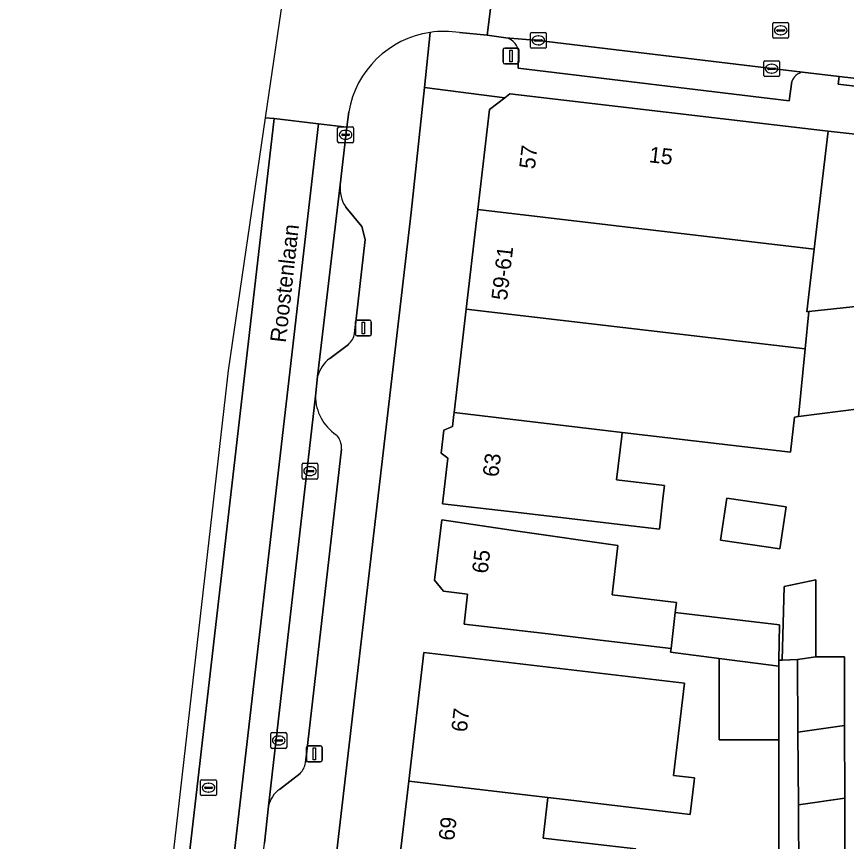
# Model space of a CAD drawing. Extents: x 162250 to 162661, y 380743 to 381606.
# Drawn here: x 162302.6 to 162355, y 381314.8 to 381366.9 of the extents above; entities that cross this region are included whole.
import ezdxf

# ---------------------------------------------------------------- set-up
doc = ezdxf.new("R2010")
doc.units = 0
for name, color, linetype in [('IMGEO_Erf', 7, 'Continuous'), ('IMGEO_Kolk', 7, 'Continuous'), ('IMGEO_Lichtmast', 7, 'Continuous'), ('IMGEO_Openbare_ruimte_label', 7, 'Continuous'), ('IMGEO_Pand', 7, 'Continuous'), ('IMGEO_Pand_nummerreeks', 7, 'Continuous'), ('IMGEO_Parkeervlak_open', 7, 'Continuous'), ('IMGEO_Rijbaan_lokaal_gesloten', 7, 'Continuous'), ('IMGEO_Rijbaan_lokaal_open', 7, 'Continuous'), ('IMGEO_Rioolput', 7, 'Continuous'), ('IMGEO_Voetpad_open', 7, 'Continuous')]:
    doc.layers.add(name, color=color, linetype=linetype)

msp = doc.modelspace()

# ---------------------------------------------------------------- linework, layer by layer
at = {"layer": 'IMGEO_Erf'}
for points in [[(162357.316, 381342.327), (162352.007, 381341.645), (162351.764, 381341.614), (162351.504, 381339.396), (162340.872, 381340.643), (162340.843, 381340.397), (162340.52, 381337.645), (162343.543, 381337.291), (162343.465, 381336.631), (162343.226, 381334.524), (162334.488, 381335.549), (162329.522, 381336.131), (162329.86, 381339.014), (162329.432, 381339.332), (162329.603, 381340.791), (162330.142, 381341.023), (162330.23, 381341.78), (162330.243, 381341.891), (162331.011, 381348.438), (162331.669, 381354.046), (162331.704, 381354.344), (162331.749, 381354.725), (162332.491, 381361.05), (162333.445, 381361.804), (162328.382, 381362.452), (162327.527, 381354.554), (162326.13, 381342.433), (162314.082, 381238.883)], [(162361.138, 381358.877), (162353.887, 381359.698), (162353.305, 381354.733), (162353.011, 381352.227), (162352.718, 381349.727), (162352.546, 381348.266), (162352.656, 381348.278), (162356.414, 381348.684)], [(162350.771, 381314.035), (162350.771, 381321.204), (162347.003, 381321.204), (162347.003, 381326.352), (162343.931, 381326.751), (162343.959, 381326.985), (162339.842, 381327.468), (162335.842, 381327.937), (162330.876, 381328.52), (162331.098, 381330.416), (162329.567, 381330.596), (162329.018, 381331.29), (162329.466, 381335.106), (162334.414, 381334.385), (162340.596, 381333.485), (162340.229, 381330.361), (162344.3, 381329.884), (162344.225, 381329.246), (162350.806, 381328.475), (162350.771, 381326.237), (162350.989, 381326.247), (162351.114, 381330.898), (162353.098, 381331.315), (162353.108, 381326.455), (162354.913, 381326.461), (162354.923, 381322.108), (162354.933, 381317.506), (162354.944, 381312.906)], [(162326.763, 381313.242), (162327.389, 381318.581), (162328.344, 381326.72), (162344.807, 381324.789), (162344.123, 381318.956), (162345.445, 381318.801), (162345.421, 381318.599), (162345.174, 381316.495), (162345.173, 381316.49), (162344.472, 381316.573), (162339.164, 381317.199), (162337.824, 381317.357), (162336.179, 381317.549), (162335.879, 381314.992), (162341.739, 381314.305)]]:
    msp.add_lwpolyline(points, dxfattribs=at)
msp.add_lwpolyline([(162347.087, 381333.833), (162347.485, 381336.488), (162351.224, 381335.927), (162350.825, 381333.272)], close=True, dxfattribs=at)
at = {"layer": 'IMGEO_Kolk'}
for p, q in [((162335.075, 381365.002), (162335.075, 381365.854)), ((162335.15, 381365.928), (162336.002, 381365.928)), ((162336.076, 381365.854), (162336.076, 381365.002)), ((162335.334, 381365.422), (162335.334, 381365.434)), ((162335.772, 381365.385), (162335.374, 381365.385)), ((162335.377, 381365.471), (162335.775, 381365.471)), ((162335.563, 381365.708), (162335.588, 381365.708)), ((162335.818, 381365.434), (162335.818, 381365.422)), ((162336.002, 381364.928), (162335.15, 381364.928)), ((162335.586, 381365.148), (162335.561, 381365.148)), ((162349.813, 381363.212), (162349.813, 381364.064)), ((162349.888, 381364.138), (162350.74, 381364.138)), ((162350.115, 381363.681), (162350.513, 381363.681)), ((162350.301, 381363.918), (162350.326, 381363.918)), ((162350.814, 381364.064), (162350.814, 381363.212)), ((162350.072, 381363.632), (162350.072, 381363.644)), ((162350.51, 381363.595), (162350.112, 381363.595)), ((162350.324, 381363.358), (162350.299, 381363.358)), ((162350.556, 381363.644), (162350.556, 381363.632)), ((162350.74, 381363.138), (162349.888, 381363.138)), ((162322.888, 381359.034), (162322.888, 381359.886)), ((162322.963, 381359.96), (162323.815, 381359.96)), ((162323.19, 381359.503), (162323.588, 381359.503)), ((162323.376, 381359.74), (162323.401, 381359.74)), ((162323.889, 381359.886), (162323.889, 381359.034)), ((162323.815, 381358.96), (162322.963, 381358.96)), ((162323.147, 381359.454), (162323.147, 381359.466)), ((162323.585, 381359.417), (162323.187, 381359.417)), ((162323.399, 381359.18), (162323.374, 381359.18)), ((162323.631, 381359.466), (162323.631, 381359.454)), ((162320.642, 381337.766), (162320.642, 381338.618)), ((162320.717, 381338.692), (162321.569, 381338.692)), ((162321.643, 381338.618), (162321.643, 381337.766)), ((162320.901, 381338.186), (162320.901, 381338.198)), ((162321.339, 381338.149), (162320.941, 381338.149)), ((162320.944, 381338.235), (162321.342, 381338.235)), ((162321.13, 381338.472), (162321.155, 381338.472)), ((162321.385, 381338.198), (162321.385, 381338.186)), ((162321.569, 381337.692), (162320.717, 381337.692)), ((162321.153, 381337.912), (162321.128, 381337.912)), ((162318.665, 381320.736), (162318.665, 381321.588)), ((162318.74, 381321.662), (162319.592, 381321.662)), ((162318.967, 381321.205), (162319.365, 381321.205)), ((162319.153, 381321.442), (162319.178, 381321.442)), ((162319.666, 381321.588), (162319.666, 381320.736)), ((162318.924, 381321.156), (162318.924, 381321.168)), ((162319.362, 381321.119), (162318.964, 381321.119)), ((162319.176, 381320.882), (162319.151, 381320.882)), ((162319.408, 381321.168), (162319.408, 381321.156)), ((162319.592, 381320.662), (162318.74, 381320.662))]:
    msp.add_line(p, q, dxfattribs=at)
for points in [[(162335.075, 381365.002), (162335.075, 381365.854)], [(162335.15, 381365.928), (162336.002, 381365.928)], [(162336.076, 381365.854), (162336.076, 381365.002)], [(162336.002, 381364.928), (162335.15, 381364.928)], [(162349.813, 381363.212), (162349.813, 381364.064)], [(162349.888, 381364.138), (162350.74, 381364.138)], [(162350.814, 381364.064), (162350.814, 381363.212)], [(162350.74, 381363.138), (162349.888, 381363.138)], [(162322.888, 381359.034), (162322.888, 381359.886)], [(162322.963, 381359.96), (162323.815, 381359.96)], [(162323.889, 381359.886), (162323.889, 381359.034)], [(162323.815, 381358.96), (162322.963, 381358.96)], [(162320.642, 381337.766), (162320.642, 381338.618)], [(162320.717, 381338.692), (162321.569, 381338.692)], [(162321.643, 381338.618), (162321.643, 381337.766)], [(162321.569, 381337.692), (162320.717, 381337.692)], [(162318.665, 381320.736), (162318.665, 381321.588)], [(162318.74, 381321.662), (162319.592, 381321.662)], [(162319.666, 381321.588), (162319.666, 381320.736)], [(162319.592, 381320.662), (162318.74, 381320.662)]]:
    msp.add_lwpolyline(points, dxfattribs=at)
for centre, radius, start, end in [((162335.152, 381365.852), 0.0765, 91.552, 178.448), ((162335.152, 381365.852), 0.0765, 91.552, 178.448), ((162336, 381365.852), 0.0765, 1.552, 88.448), ((162336, 381365.852), 0.0765, 1.552, 88.448), ((162335.374, 381365.431), 0.0403, 85.8775, 175.7526), ((162335.371, 381365.421), 0.0366, 178.938, 274.7102), ((162335.775, 381365.428), 0.043, 264.8664, 352.4533), ((162335.779, 381365.433), 0.0386, 1.7309, 96.639), ((162335.152, 381365.004), 0.0765, 181.552, 268.448), ((162335.152, 381365.004), 0.0765, 181.552, 268.448), ((162336, 381365.004), 0.0765, 271.552, 358.448), ((162336, 381365.004), 0.0765, 271.552, 358.448), ((162349.89, 381364.062), 0.0765, 91.552, 178.448), ((162349.89, 381364.062), 0.0765, 91.552, 178.448), ((162350.112, 381363.641), 0.0403, 85.8775, 175.7526), ((162350.517, 381363.643), 0.0386, 1.7309, 96.639), ((162350.738, 381364.062), 0.0765, 1.552, 88.448), ((162350.738, 381364.062), 0.0765, 1.552, 88.448), ((162349.89, 381363.214), 0.0765, 181.552, 268.448), ((162349.89, 381363.214), 0.0765, 181.552, 268.448), ((162350.109, 381363.631), 0.0366, 178.938, 274.7102), ((162350.513, 381363.638), 0.043, 264.8664, 352.4533), ((162350.738, 381363.214), 0.0765, 271.552, 358.448), ((162350.738, 381363.214), 0.0765, 271.552, 358.448), ((162322.965, 381359.884), 0.0765, 91.552, 178.448), ((162322.965, 381359.884), 0.0765, 91.552, 178.448), ((162323.187, 381359.463), 0.0403, 85.8775, 175.7526), ((162323.592, 381359.465), 0.0386, 1.7309, 96.639), ((162323.813, 381359.884), 0.0765, 1.552, 88.448), ((162323.813, 381359.884), 0.0765, 1.552, 88.448), ((162322.965, 381359.036), 0.0765, 181.552, 268.448), ((162322.965, 381359.036), 0.0765, 181.552, 268.448), ((162323.184, 381359.453), 0.0366, 178.938, 274.7102), ((162323.588, 381359.46), 0.043, 264.8664, 352.4533), ((162323.813, 381359.036), 0.0765, 271.552, 358.448), ((162323.813, 381359.036), 0.0765, 271.552, 358.448), ((162320.719, 381338.616), 0.0765, 91.552, 178.448), ((162320.719, 381338.616), 0.0765, 91.552, 178.448), ((162321.567, 381338.616), 0.0765, 1.552, 88.448), ((162321.567, 381338.616), 0.0765, 1.552, 88.448), ((162320.941, 381338.195), 0.0403, 85.8775, 175.7526), ((162320.938, 381338.185), 0.0366, 178.938, 274.7102), ((162321.342, 381338.192), 0.043, 264.8664, 352.4533), ((162321.346, 381338.197), 0.0386, 1.7309, 96.639), ((162320.719, 381337.768), 0.0765, 181.552, 268.448), ((162320.719, 381337.768), 0.0765, 181.552, 268.448), ((162321.567, 381337.768), 0.0765, 271.552, 358.448), ((162321.567, 381337.768), 0.0765, 271.552, 358.448), ((162318.742, 381321.586), 0.0765, 91.552, 178.448), ((162318.742, 381321.586), 0.0765, 91.552, 178.448), ((162318.964, 381321.165), 0.0403, 85.8775, 175.7526), ((162319.369, 381321.167), 0.0386, 1.7309, 96.639), ((162319.59, 381321.586), 0.0765, 1.552, 88.448), ((162319.59, 381321.586), 0.0765, 1.552, 88.448), ((162318.742, 381320.738), 0.0765, 181.552, 268.448), ((162318.742, 381320.738), 0.0765, 181.552, 268.448), ((162318.961, 381321.155), 0.0366, 178.938, 274.7102), ((162319.365, 381321.162), 0.043, 264.8664, 352.4533), ((162319.59, 381320.738), 0.0765, 271.552, 358.448), ((162319.59, 381320.738), 0.0765, 271.552, 358.448)]:
    msp.add_arc(centre, radius, start, end, dxfattribs=at)
for centre, major_axis, ratio, start_param, end_param in [((162335.562, 381365.428), (-0.387, 0.002), 0.722429, 4.712389, 7.853982), ((162335.587, 381365.428), (-0.39, 0.002), 0.717154, 1.570796, 4.712389), ((162350.3, 381363.638), (-0.387, 0.002), 0.722429, 4.712389, 7.853982), ((162350.325, 381363.638), (-0.39, 0.002), 0.717154, 1.570796, 4.712389), ((162323.375, 381359.46), (-0.387, 0.002), 0.722429, 4.712389, 7.853982), ((162323.4, 381359.46), (-0.39, 0.002), 0.717154, 1.570796, 4.712389), ((162321.129, 381338.192), (-0.387, 0.002), 0.722429, 4.712389, 7.853982), ((162321.154, 381338.192), (-0.39, 0.002), 0.717154, 1.570796, 4.712389), ((162319.152, 381321.162), (-0.387, 0.002), 0.722429, 4.712389, 7.853982), ((162319.177, 381321.162), (-0.39, 0.002), 0.717154, 1.570796, 4.712389)]:
    msp.add_ellipse(centre, major_axis=major_axis, ratio=ratio, start_param=start_param, end_param=end_param, dxfattribs=at)
at = {"layer": 'IMGEO_Lichtmast'}
for p, q in [((162333.35, 381364.043), (162333.35, 381364.843)), ((162333.35, 381364.843), (162333.35, 381364.043)), ((162333.45, 381364.943), (162334.24, 381364.943)), ((162334.24, 381364.943), (162333.45, 381364.943)), ((162334.34, 381364.843), (162334.34, 381364.043)), ((162334.34, 381364.043), (162334.34, 381364.843)), ((162334.24, 381363.943), (162333.45, 381363.943)), ((162333.45, 381363.943), (162334.24, 381363.943)), ((162324.016, 381346.841), (162324.016, 381347.641)), ((162324.016, 381347.641), (162324.016, 381346.841)), ((162324.116, 381347.741), (162324.906, 381347.741)), ((162324.906, 381347.741), (162324.116, 381347.741)), ((162325.006, 381347.641), (162325.006, 381346.841)), ((162325.006, 381346.841), (162325.006, 381347.641)), ((162324.906, 381346.741), (162324.116, 381346.741)), ((162324.116, 381346.741), (162324.906, 381346.741)), ((162320.919, 381319.919), (162320.919, 381320.719)), ((162320.919, 381320.719), (162320.919, 381319.919)), ((162321.019, 381320.819), (162321.809, 381320.819)), ((162321.809, 381320.819), (162321.019, 381320.819)), ((162321.909, 381320.719), (162321.909, 381319.919)), ((162321.909, 381319.919), (162321.909, 381320.719)), ((162321.809, 381319.819), (162321.019, 381319.819)), ((162321.019, 381319.819), (162321.809, 381319.819))]:
    msp.add_line(p, q, dxfattribs=at)
for points in [[(162333.77, 381364.818), (162333.92, 381364.818), (162333.92, 381364.068), (162333.77, 381364.068), (162333.77, 381364.818)], [(162324.436, 381347.616), (162324.586, 381347.616), (162324.586, 381346.866), (162324.436, 381346.866), (162324.436, 381347.616)], [(162321.339, 381320.694), (162321.489, 381320.694), (162321.489, 381319.944), (162321.339, 381319.944), (162321.339, 381320.694)]]:
    msp.add_lwpolyline(points, dxfattribs=at)
for centre, start, end in [((162333.45, 381364.843), 90, 180), ((162333.45, 381364.843), 90, 180), ((162334.24, 381364.843), 0, 90), ((162334.24, 381364.843), 360, 90), ((162333.45, 381364.043), 180, 270), ((162333.45, 381364.043), 180, 270), ((162334.24, 381364.043), 270, 0), ((162334.24, 381364.043), 270, 0), ((162324.116, 381347.641), 90, 180), ((162324.116, 381347.641), 90, 180), ((162324.906, 381347.641), 0, 90), ((162324.906, 381347.641), 360, 90), ((162324.116, 381346.841), 180, 270), ((162324.116, 381346.841), 180, 270), ((162324.906, 381346.841), 270, 0), ((162324.906, 381346.841), 270, 0), ((162321.019, 381320.719), 90, 180), ((162321.019, 381320.719), 90, 180), ((162321.809, 381320.719), 0, 90), ((162321.809, 381320.719), 360, 90), ((162321.019, 381319.919), 180, 270), ((162321.019, 381319.919), 180, 270), ((162321.809, 381319.919), 270, 0), ((162321.809, 381319.919), 270, 0)]:
    msp.add_arc(centre, 0.1, start, end, dxfattribs=at)
at = {"layer": 'IMGEO_Pand'}
for points in [[(162331.749, 381354.725), (162353.011, 381352.227), (162353.305, 381354.733), (162353.887, 381359.698), (162333.767, 381362.058), (162333.445, 381361.804), (162332.491, 381361.05)], [(162353.011, 381352.227), (162331.749, 381354.725), (162331.704, 381354.344), (162331.669, 381354.046), (162331.011, 381348.438), (162352.444, 381345.925), (162352.656, 381348.278), (162352.546, 381348.266), (162352.718, 381349.727)], [(162352.007, 381341.645), (162357.316, 381342.327), (162357.009, 381345.169), (162356.796, 381345.146), (162356.414, 381348.684), (162352.656, 381348.278), (162352.444, 381345.925)], [(162352.007, 381341.645), (162352.444, 381345.925), (162331.011, 381348.438), (162330.243, 381341.891), (162340.872, 381340.643), (162351.504, 381339.396), (162351.764, 381341.614)], [(162340.52, 381337.645), (162340.843, 381340.397), (162340.872, 381340.643), (162330.243, 381341.891), (162330.23, 381341.78), (162330.142, 381341.023), (162329.603, 381340.791), (162329.432, 381339.332), (162329.86, 381339.014), (162329.522, 381336.131), (162334.488, 381335.549), (162343.226, 381334.524), (162343.465, 381336.631), (162343.543, 381337.291)], [(162347.087, 381333.833), (162350.825, 381333.272), (162351.224, 381335.927), (162347.485, 381336.488)], [(162340.596, 381333.485), (162334.414, 381334.385), (162329.466, 381335.106), (162329.018, 381331.29), (162329.567, 381330.596), (162331.098, 381330.416), (162330.876, 381328.52), (162335.842, 381327.937), (162339.842, 381327.468), (162343.959, 381326.985), (162344.225, 381329.246), (162344.3, 381329.884), (162340.229, 381330.361)], [(162351.947, 381326.289), (162353.108, 381326.455), (162353.098, 381331.315), (162351.114, 381330.898), (162350.989, 381326.247)], [(162344.225, 381329.246), (162343.959, 381326.985), (162343.931, 381326.751), (162347.003, 381326.352), (162350.771, 381325.862), (162350.771, 381326.237), (162350.806, 381328.475)], [(162327.389, 381318.581), (162336.179, 381317.549), (162337.824, 381317.357), (162339.164, 381317.199), (162344.472, 381316.573), (162345.173, 381316.49), (162345.174, 381316.495), (162345.421, 381318.599), (162345.445, 381318.801), (162344.123, 381318.956), (162344.807, 381324.789), (162328.344, 381326.72)], [(162351.947, 381326.289), (162351.978, 381321.684), (162354.923, 381322.108), (162354.913, 381326.461), (162353.108, 381326.455)], [(162347.003, 381326.352), (162347.003, 381321.204), (162350.771, 381321.204), (162350.771, 381325.862)], [(162352.009, 381317.086), (162354.933, 381317.506), (162354.923, 381322.108), (162351.978, 381321.684)], [(162336.179, 381317.549), (162327.389, 381318.581), (162326.763, 381313.242), (162326.794, 381313.238), (162341.413, 381311.524), (162341.739, 381314.305), (162335.879, 381314.992)], [(162352.009, 381317.086), (162352.04, 381312.489), (162354.944, 381312.906), (162354.933, 381317.506)]]:
    msp.add_lwpolyline(points, close=True, dxfattribs=at)
at = {"layer": 'IMGEO_Parkeervlak_open'}
for points in [[(162335.576, 381365.429), (162333.525, 381365.596)], [(162352.274, 381363.417), (162335.576, 381365.429)], [(162334.323, 381364.598), (162334.304, 381363.671), (162351.43, 381361.612), (162351.591, 381362.82)], [(162323.053, 381356.29), (162321.621, 381344.181)], [(162323.958, 381346.887), (162324.636, 381352.842), (162324.415, 381353.657), (162323.402, 381354.884)], [(162322.388, 381345.317), (162323.573, 381346.209)], [(162321.484, 381342.938), (162318.523, 381317.019)], [(162320.851, 381319.748), (162323.125, 381339.588)], [(162319.206, 381318.068), (162320.525, 381319.084)]]:
    msp.add_lwpolyline(points, dxfattribs=at)
for centre, radius, start, end in [((162333.308, 381364.604), 1.015, 359.6383, 77.6533), ((162352.421, 381362.56), 0.87, 99.7324, 162.58), ((162325.185, 381356.073), 2.143, 174.1859, 213.6947), ((162322.724, 381347.14), 1.26, 312.3856, 348.4345), ((162323.597, 381343.674), 2.04, 126.3433, 165.6041), ((162324.459, 381342.957), 2.975, 180.3587, 236.0193), ((162322.018, 381339.695), 1.112, 354.4607, 45.6177), ((162319.674, 381319.914), 1.188, 315.7133, 351.988), ((162320.209, 381316.668), 1.722, 125.6243, 168.2397)]:
    msp.add_arc(centre, radius, start, end, dxfattribs=at)
at = {"layer": 'IMGEO_Rijbaan_lokaal_gesloten'}
for points in [[(162318.31, 381360.535), (162315.97, 381344.552), (162303.714, 381236.926), (162302.598, 381226.919), (162303.468, 381226.833), (162318.873, 381360.48)], [(162318.256, 381314.678), (162318.523, 381317.019), (162321.484, 381342.938), (162321.621, 381344.181), (162323.053, 381356.29), (162323.469, 381359.935), (162321.674, 381360.143), (162306.264, 381226.555), (162307.997, 381226.383), (162308.085, 381226.743), (162308.157, 381227.247), (162312.784, 381267.394), (162312.897, 381268.512)]]:
    msp.add_lwpolyline(points, close=True, dxfattribs=at)
at = {"layer": 'IMGEO_Rijbaan_lokaal_open'}
for points in [[(162326.057, 381376.827), (162326.277, 381378.617), (162324.497, 381378.848), (162321.673, 381379.215), (162321.057, 381379.295), (162321.057, 381379.295), (162319.615, 381369.448), (162318.31, 381360.535)], [(162330.579, 381365.92), (162332.334, 381365.76), (162332.888, 381370.148), (162331.099, 381370.386)], [(162318.31, 381360.535), (162318.873, 381360.48), (162321.674, 381360.143), (162323.469, 381359.935), (162323.587, 381360.916)]]:
    msp.add_lwpolyline(points, dxfattribs=at)
for points in [[(162355.136, 381367.589), (162353.99, 381367.718), (162353.883, 381367.738), (162334.237, 381369.996), (162332.888, 381370.148), (162332.334, 381365.76), (162333.525, 381365.596), (162335.576, 381365.429), (162352.274, 381363.417), (162354.574, 381363.147), (162360.607, 381362.439), (162370.812, 381361.312), (162371.314, 381365.763)], [(162321.674, 381360.143), (162318.873, 381360.48), (162303.468, 381226.833), (162306.264, 381226.555)]]:
    msp.add_lwpolyline(points, close=True, dxfattribs=at)
for centre, radius, start, end in [((162329.623, 381359.869), 6.126, 98.35, 170.1613), ((162329.623, 381359.875), 6.12, 81.0159, 98.3634)]:
    msp.add_arc(centre, radius, start, end, dxfattribs=at)
at = {"layer": 'IMGEO_Rioolput'}
for p, q in [((162350.389, 381365.637), (162350.389, 381366.489)), ((162350.464, 381366.563), (162351.316, 381366.563)), ((162350.877, 381366.343), (162350.902, 381366.343)), ((162351.39, 381366.489), (162351.39, 381365.637)), ((162350.648, 381366.057), (162350.648, 381366.069)), ((162351.086, 381366.02), (162350.688, 381366.02)), ((162350.691, 381366.106), (162351.089, 381366.106)), ((162350.9, 381365.783), (162350.875, 381365.783)), ((162351.132, 381366.069), (162351.132, 381366.057)), ((162351.316, 381365.563), (162350.464, 381365.563)), ((162314.227, 381317.751), (162314.227, 381318.603)), ((162314.302, 381318.677), (162315.154, 381318.677)), ((162315.228, 381318.603), (162315.228, 381317.751)), ((162314.486, 381318.171), (162314.486, 381318.183)), ((162314.924, 381318.134), (162314.526, 381318.134)), ((162314.529, 381318.22), (162314.927, 381318.22)), ((162314.715, 381318.457), (162314.74, 381318.457)), ((162314.97, 381318.183), (162314.97, 381318.171)), ((162315.154, 381317.677), (162314.302, 381317.677)), ((162314.738, 381317.897), (162314.713, 381317.897))]:
    msp.add_line(p, q, dxfattribs=at)
for points in [[(162350.389, 381365.637), (162350.389, 381366.489)], [(162350.464, 381366.563), (162351.316, 381366.563)], [(162351.39, 381366.489), (162351.39, 381365.637)], [(162351.316, 381365.563), (162350.464, 381365.563)], [(162314.227, 381317.751), (162314.227, 381318.603)], [(162314.302, 381318.677), (162315.154, 381318.677)], [(162315.228, 381318.603), (162315.228, 381317.751)], [(162315.154, 381317.677), (162314.302, 381317.677)]]:
    msp.add_lwpolyline(points, dxfattribs=at)
for centre, radius, start, end in [((162350.466, 381366.487), 0.0765, 91.552, 178.448), ((162350.466, 381366.487), 0.0765, 91.552, 178.448), ((162351.314, 381366.487), 0.0765, 1.552, 88.448), ((162351.314, 381366.487), 0.0765, 1.552, 88.448), ((162350.688, 381366.066), 0.0403, 85.8775, 175.7526), ((162350.685, 381366.056), 0.0366, 178.938, 274.7102), ((162351.089, 381366.063), 0.043, 264.8664, 352.4533), ((162351.093, 381366.068), 0.0386, 1.7309, 96.639), ((162350.466, 381365.639), 0.0765, 181.552, 268.448), ((162350.466, 381365.639), 0.0765, 181.552, 268.448), ((162351.314, 381365.639), 0.0765, 271.552, 358.448), ((162351.314, 381365.639), 0.0765, 271.552, 358.448), ((162314.304, 381318.601), 0.0765, 91.552, 178.448), ((162314.304, 381318.601), 0.0765, 91.552, 178.448), ((162315.152, 381318.601), 0.0765, 1.552, 88.448), ((162315.152, 381318.601), 0.0765, 1.552, 88.448), ((162314.526, 381318.18), 0.0403, 85.8775, 175.7526), ((162314.523, 381318.17), 0.0366, 178.938, 274.7102), ((162314.927, 381318.177), 0.043, 264.8664, 352.4533), ((162314.931, 381318.182), 0.0386, 1.7309, 96.639), ((162314.304, 381317.753), 0.0765, 181.552, 268.448), ((162314.304, 381317.753), 0.0765, 181.552, 268.448), ((162315.152, 381317.753), 0.0765, 271.552, 358.448), ((162315.152, 381317.753), 0.0765, 271.552, 358.448)]:
    msp.add_arc(centre, radius, start, end, dxfattribs=at)
for centre, major_axis, ratio, start_param, end_param in [((162350.876, 381366.063), (-0.387, 0.002), 0.722429, 4.712389, 7.853982), ((162350.901, 381366.063), (-0.39, 0.002), 0.717154, 1.570796, 4.712389), ((162314.714, 381318.177), (-0.387, 0.002), 0.722429, 4.712389, 7.853982), ((162314.739, 381318.177), (-0.39, 0.002), 0.717154, 1.570796, 4.712389)]:
    msp.add_ellipse(centre, major_axis=major_axis, ratio=ratio, start_param=start_param, end_param=end_param, dxfattribs=at)
at = {"layer": 'IMGEO_Voetpad_open'}
for points in [[(162313.954, 381237.787), (162314.082, 381238.883), (162326.13, 381342.433), (162327.527, 381354.554), (162328.382, 381362.452), (162328.733, 381365.93)], [(162328.733, 381365.93), (162328.382, 381362.452), (162333.445, 381361.804), (162333.767, 381362.058), (162353.887, 381359.698), (162361.138, 381358.877), (162372.694, 381357.569), (162375.752, 381357.241), (162375.645, 381357.877)], [(162333.525, 381365.596), (162332.334, 381365.76), (162330.579, 381365.92)], [(162351.591, 381362.82), (162351.43, 381361.612), (162334.304, 381363.671), (162334.323, 381364.598)], [(162371.854, 381361.197), (162370.812, 381361.312), (162360.607, 381362.439), (162360.547, 381361.943), (162354.513, 381362.651), (162354.574, 381363.147), (162352.274, 381363.417)], [(162323.587, 381360.916), (162323.469, 381359.935), (162323.053, 381356.29)], [(162323.402, 381354.884), (162324.415, 381353.657), (162324.636, 381352.842), (162323.958, 381346.887)], [(162323.573, 381346.209), (162322.388, 381345.317)], [(162321.621, 381344.181), (162321.484, 381342.938)], [(162323.125, 381339.588), (162320.851, 381319.748)], [(162352.04, 381312.489), (162352.009, 381317.086), (162351.978, 381321.684), (162351.947, 381326.289), (162350.989, 381326.247), (162350.771, 381326.237), (162350.771, 381325.862), (162350.771, 381321.204), (162350.771, 381314.035)], [(162320.525, 381319.084), (162319.206, 381318.068)], [(162318.523, 381317.019), (162318.256, 381314.678)]]:
    msp.add_lwpolyline(points, dxfattribs=at)
msp.add_lwpolyline([(162354.574, 381363.147), (162354.513, 381362.651), (162360.547, 381361.943), (162360.607, 381362.439)], close=True, dxfattribs=at)
for centre, radius, start, end in [((162329.623, 381359.869), 6.126, 98.35, 170.1613), ((162329.623, 381359.875), 6.12, 81.0159, 98.3634), ((162333.308, 381364.604), 1.015, 359.6383, 77.6533), ((162352.421, 381362.56), 0.87, 99.7324, 162.58), ((162325.185, 381356.073), 2.143, 174.1859, 213.6947), ((162322.724, 381347.14), 1.26, 312.3856, 348.4345), ((162323.597, 381343.674), 2.04, 126.3433, 165.6041), ((162324.459, 381342.957), 2.975, 180.3587, 236.0193), ((162322.018, 381339.695), 1.112, 354.4607, 45.6177), ((162319.674, 381319.914), 1.188, 315.7133, 351.988), ((162320.209, 381316.668), 1.722, 125.6243, 168.2397)]:
    msp.add_arc(centre, radius, start, end, dxfattribs=at)

# ---------------------------------------------------------------- texts
at = {"layer": 'IMGEO_Openbare_ruimte_label'}
msp.add_text('Roostenlaan', height=1, rotation=83.5713, dxfattribs=at).set_placement((162319.61, 381346.284))
at = {"layer": 'IMGEO_Pand_nummerreeks'}
for s, rotation, p in [('57', 83.3089, (162335.349, 381357.256)), ('15', 353.31, (162342.53, 381357.728)), ('59-61', 83.3081, (162333.589, 381348.956)), ('63', 82.8669, (162333.035, 381337.784)), ('65', 83.3023, (162332.366, 381331.684)), ('67', 83.3081, (162331.053, 381321.658)), ('69', 83.3081, (162330.247, 381314.787))]:
    msp.add_text(s, height=1, rotation=rotation, dxfattribs=at).set_placement(p)

doc.saveas('drawing.dxf')
